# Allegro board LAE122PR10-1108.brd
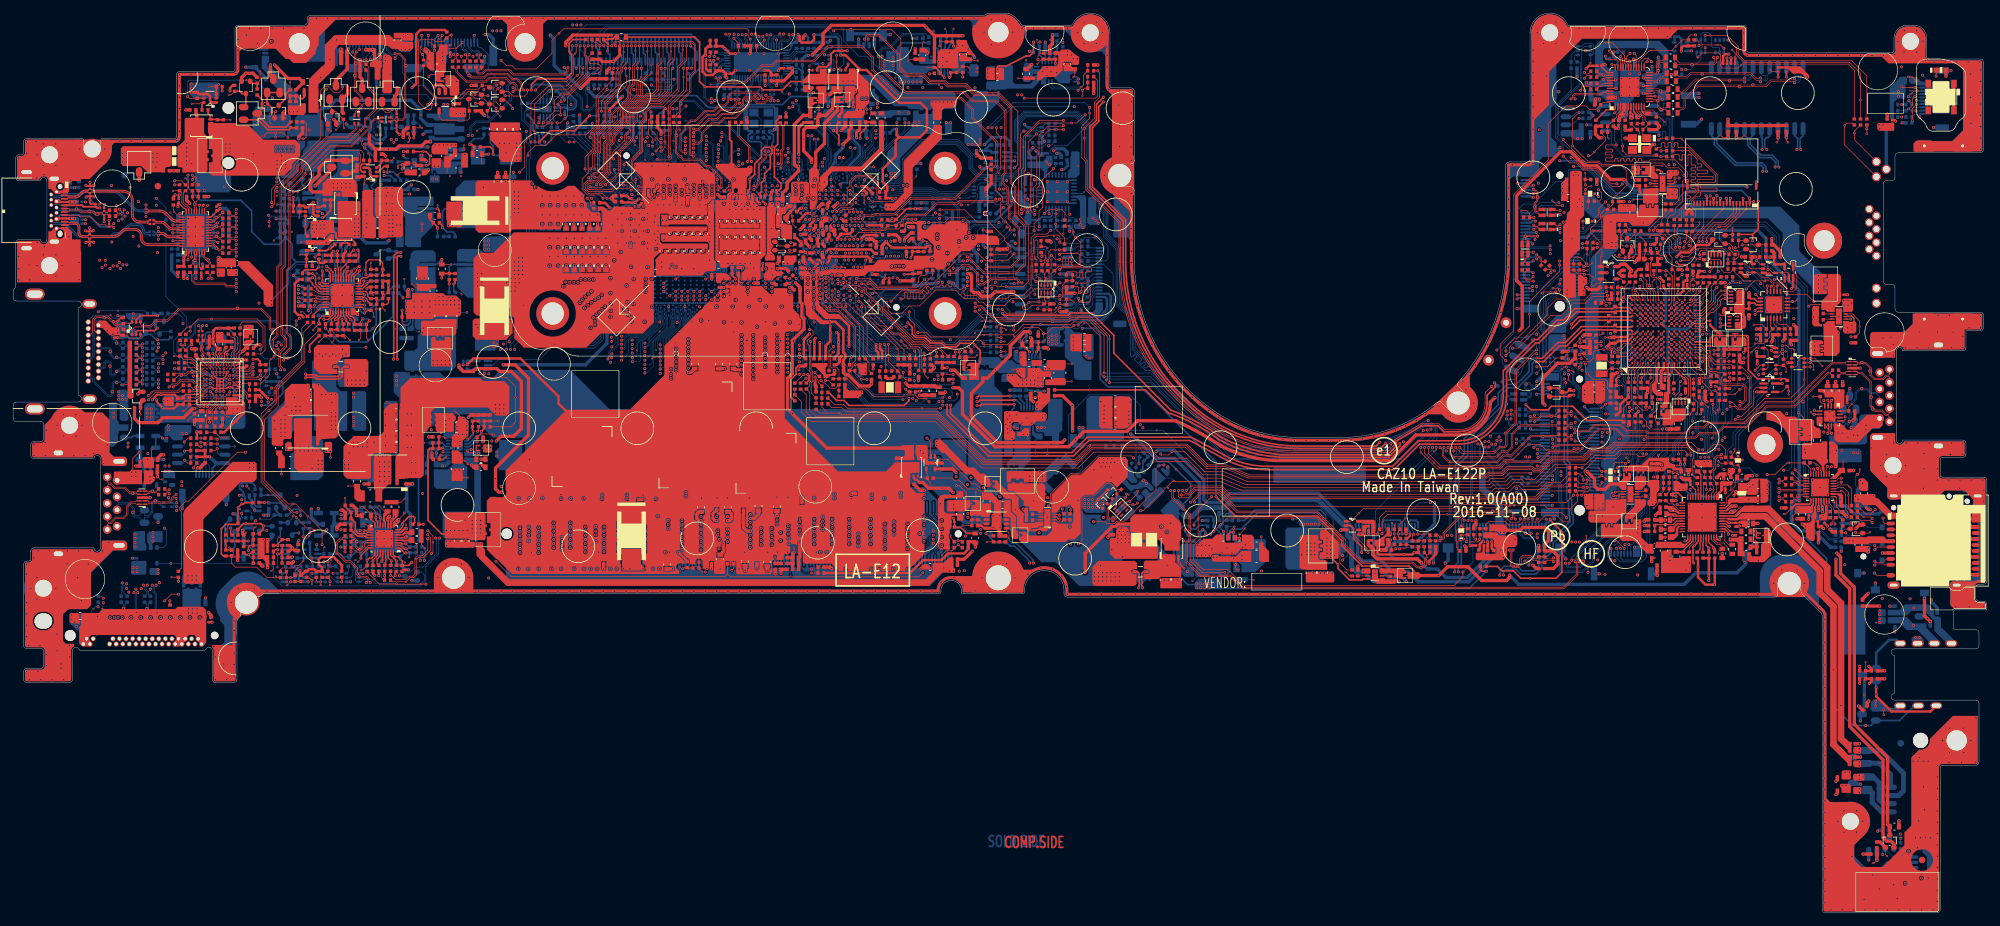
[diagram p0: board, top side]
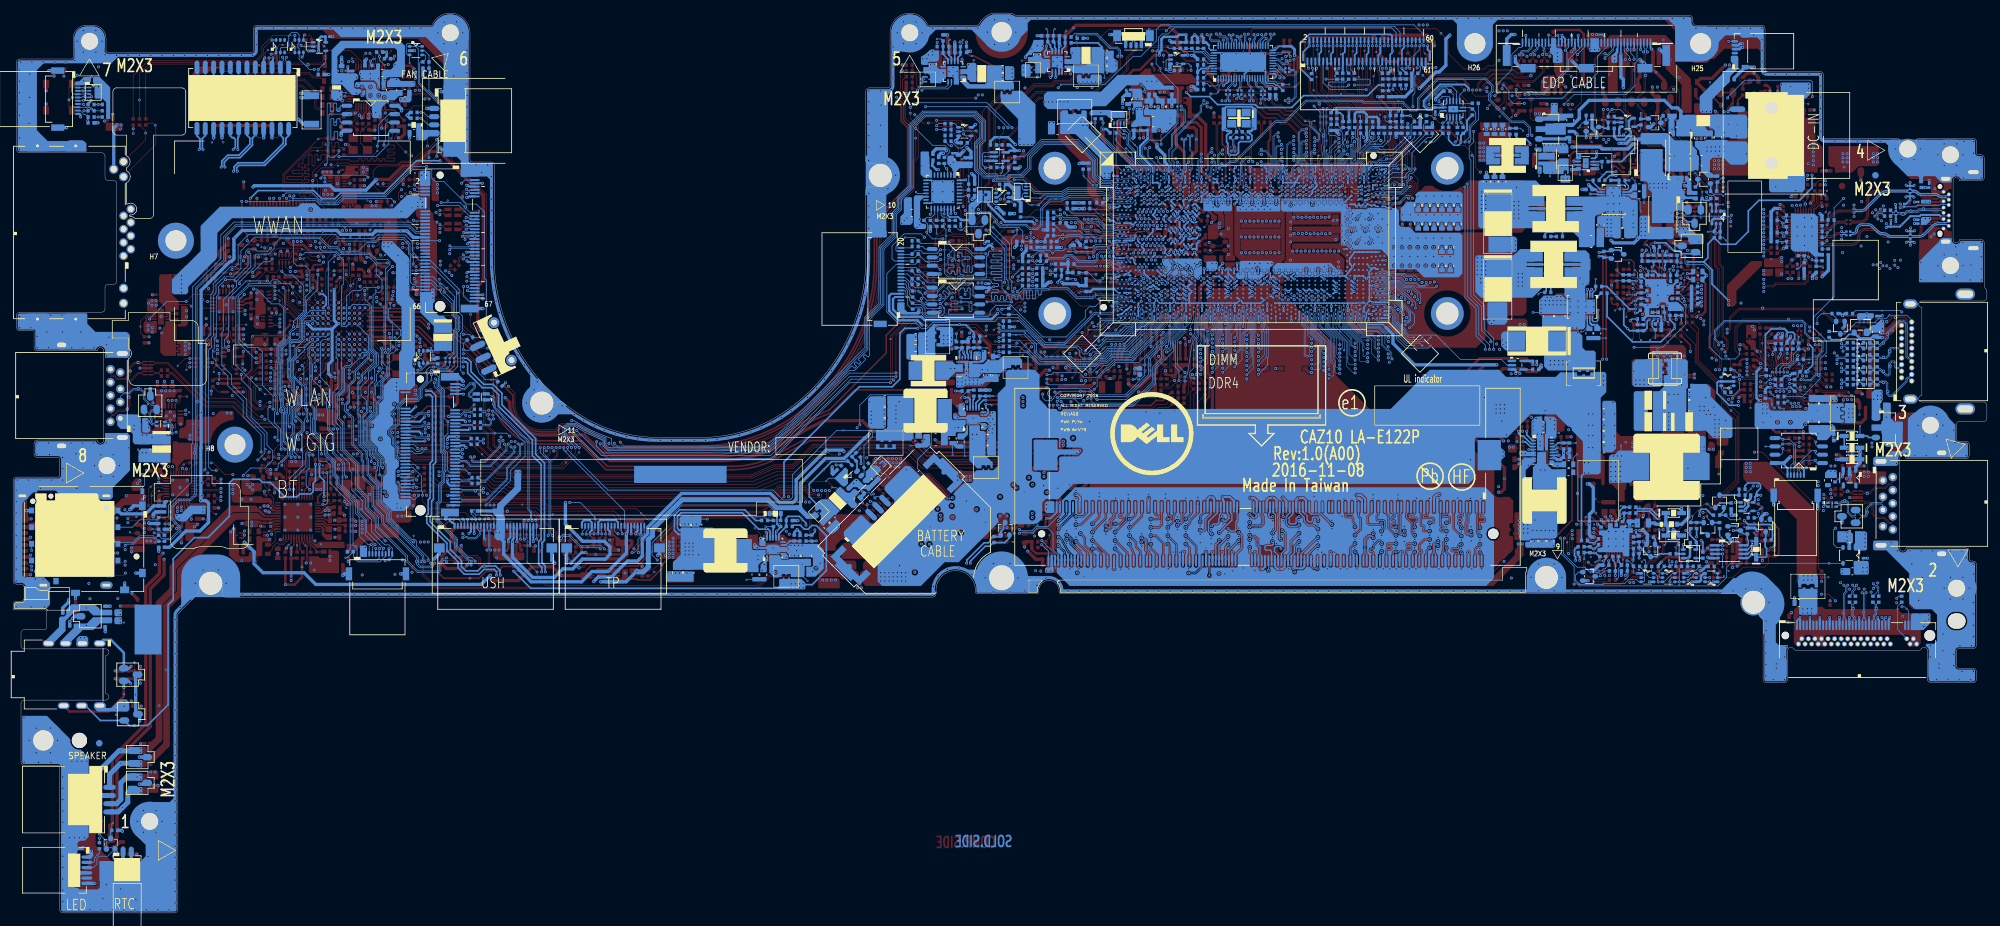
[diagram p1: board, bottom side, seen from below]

Outline 300.7 x 137.2 mm; copper layers: TOP, GND1, IN1, VCC, IN2, IN3, GND2, BOTTOM. Coordinates in mm from the lower left corner of the outline.

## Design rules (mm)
net group 20: nets DDR_DRAMRST#_R EMMC_RCOMP
net group DIFFPAIR0: nets PCIE_PTX_C_DRX_N1 PCIE_PTX_C_DRX_P1
net group DIFFPAIR1: nets PCIE_PTX_DRX_N1 PCIE_PTX_DRX_P1
net group DIFFPAIR2: nets PCIE_PRX_DTX_N1 PCIE_PRX_DTX_P1
net group DIFFPAIR3: nets PCIE_PRX_C_DTX_N1 PCIE_PRX_C_DTX_P1
net group DIFFPAIR4: nets SATA_PRX_DTX_N1 SATA_PRX_DTX_P1
net group EXPANDER_GPU_SMCLK: nets EXPANDER_GPU_SMCLK EXPANDER_GPU_SMDAT
net group HDMI_CTRL_CLK: nets HDMI_CTRL_CLK HDMI_CTRL_DATA
net group HDMI_L_CLK: nets HDMI_L_CLKN HDMI_L_CLKP
net group HDMI_L_TX_0: nets HDMI_L_TX_N0 HDMI_L_TX_P0
net group HDMI_L_TX_1: nets HDMI_L_TX_N1 HDMI_L_TX_P1
net group HDMI_L_TX_2: nets HDMI_L_TX_N2 HDMI_L_TX_P2
net group INT_SPK_L: nets INT_SPK_L+ INT_SPK_L-
net group INT_SPK_R: nets INT_SPK_R+ INT_SPK_R-
net group INT_SPKR_L: nets INT_SPKR_L+ INT_SPKR_L-
net group INT_SPKR_R: nets INT_SPKR_R+ INT_SPKR_R-
net group ISH_I2C2_SCL: nets ISH_I2C2_SCL ISH_I2C2_SDA
net group LAN_MDI0: nets LAN_MDIN0 LAN_MDIP0
net group LAN_MDI0_L: nets LAN_MDIN0_L LAN_MDIP0_L
net group LAN_MDI1: nets LAN_MDIN1 LAN_MDIP1
net group LAN_MDI1_L: nets LAN_MDIN1_L LAN_MDIP1_L
net group LAN_MDI2: nets LAN_MDIN2 LAN_MDIP2
net group LAN_MDI2_L: nets LAN_MDIN2_L LAN_MDIP2_L
net group LAN_MDI3: nets LAN_MDIN3 LAN_MDIP3
net group LAN_MDI3_L: nets LAN_MDIN3_L LAN_MDIP3_L
net group LPSS_UART2_XD: nets LPSS_UART2_RXD LPSS_UART2_TXD
net group MEM_SMB: nets MEM_SMBCLK MEM_SMBDATA
net group MSCLK: nets MSCLK MSDATA
net group PACIE: nets CLK_PCIE_N0 CLK_PCIE_P0
net group PBAT_CHARGER_SMB: nets PBAT_CHARGER_SMBCLK PBAT_CHARGER_SMBDAT
net group PCIE_PRX_C_DTX_9: nets PCIE_PRX_C_DTX_N9 PCIE_PRX_C_DTX_P9
net group PCIE_PRX_DTX_3: nets PCIE_PRX_DTX_N3 PCIE_PRX_DTX_P3
net group PCIE_PRX_DTX_9: nets PCIE_PRX_DTX_N9 PCIE_PRX_DTX_P9
net group PCIE_PTX_C_DRX_3: nets PCIE_PTX_C_DRX_N3 PCIE_PTX_C_DRX_P3
net group PCIE_PTX_C_DRX_4: nets PCIE_PTX_C_DRX_N4 PCIE_PTX_C_DRX_P4
net group PCIE_PTX_C_DRX_9: nets PCIE_PTX_C_DRX_N9 PCIE_PTX_C_DRX_P9
net group PCIE_PTX_DRX_3: nets PCIE_PTX_DRX_N3 PCIE_PTX_DRX_P3
net group PCIE_PTX_DRX_9: nets PCIE_PTX_DRX_N9 PCIE_PTX_DRX_P9
net group REM_DIODE1: nets REM_DIODE1_N REM_DIODE1_P
net group REM_DIODE2: nets REM_DIODE2_N REM_DIODE2_P
net group REM_DIODE4: nets REM_DIODE4_N REM_DIODE4_P
net group RJ45_MDI0: nets RJ45_MDIN0 RJ45_MDIP0
net group RJ45_MDI1: nets RJ45_MDIN1 RJ45_MDIP1
net group RJ45_MDI2: nets RJ45_MDIN2 RJ45_MDIP2
net group RJ45_MDI3: nets RJ45_MDIN3 RJ45_MDIP3
net group SENSE: nets VCC_GT_SENSE VSS_GT_SENSE
net group SML0_SMB: nets SML0_SMBCLK SML0_SMBDATA
net group SML1_SMB: nets SML1_SMBCLK SML1_SMBDATA
net group SW_USB20_1: nets SW_USB20_N1 SW_USB20_P1
net group TBTA_AUX_C: nets TBTA_AUXN_C TBTA_AUXP_C
net group TBTA_LSX_R: nets TBTA_LSRX_R TBTA_LSTX_R
net group UPD1_SMBD: nets UPD1_SMBCLK_Q UPD1_SMBDAT_Q
net group USB3_PRX_C_DTX_P6: nets USB3_PRX_C_DTX_N6 USB3_PRX_C_DTX_P6
net group USB3_PRX_DTX_1: nets USB3_PRX_DTX_N1 USB3_PRX_DTX_P1
net group USB3_PRX_DTX_2: nets USB3_PRX_DTX_N2 USB3_PRX_DTX_P2
net group USB3_PRX_DTX_3: nets USB3_PRX_DTX_N3 USB3_PRX_DTX_P3
net group USB3_PRX_L_DTX_2: nets USB3_PRX_L_DTX_N2 USB3_PRX_L_DTX_P2
net group USB3_PTX_C_DRX_1: nets USB3_PTX_C_DRX_N1 USB3_PTX_C_DRX_P1
net group USB3_PTX_C_DRX_2: nets USB3_PTX_C_DRX_N2 USB3_PTX_C_DRX_P2
net group USB3_PTX_C_DRX_3: nets USB3_PTX_C_DRX_N3 USB3_PTX_C_DRX_P3
net group USB3_PTX_DRX_1: nets USB3_PTX_DRX_N1 USB3_PTX_DRX_P1
net group USB3_PTX_DRX_2: nets USB3_PTX_DRX_N2 USB3_PTX_DRX_P2
net group USB3_PTX_L_DRX_2: nets USB3_PTX_L_DRX_N2 USB3_PTX_L_DRX_P2
net group USB20_1: nets USB20_N1 USB20_P1
net group USB20_2: nets USB20_N2 USB20_P2
net group USB20_2_R: nets USB20_N2_R USB20_P2_R
net group USB20_4: nets USB20_N4 USB20_P4
net group USB20_4_L: nets USB20_N4_L USB20_P4_L
net group USB20_5: nets USB20_N5 USB20_P5
net group USB20_5_R: nets USB20_N5_R USB20_P5_R
net group USB20_7_L: nets USB20_N7_L USB20_P7_L
net group USB20_8: nets USB20_N8 USB20_P8
net group USB20_8_R: nets USB20_N8_R USB20_P8_R
net group USB20_10: nets USB20_N10 USB20_P10
net group VCCSENSE: nets VCCSENSE VSSSENSE
net group VSA_SEN: nets VSA_SEN+ VSA_SEN-
net group VSSIO_SENSE: nets VCCIO_SENSE VSSIO_SENSE
net group 10: nets AUD_HP_NB_SENSE AUD_HP_OUT_L AUD_HP_OUT_L1 AUD_HP_OUT_R AUD_HP_OUT_R1 AUD_SENSE_A
net group 15: nets BC_CLK_ECE1117 CLK_TP_SIO_R CPU_DP2_CTRL_CLK CPU_XDP_TCLK DAT_TP_SIO_I2C_CLK DDR_XDP_WAN_SMBCLK DMIC_CLK0 DMIC_CLK_CODEC ESPI_CLK_5105 HDA_BIT_CLK HDA_BIT_CLK_R I2C1_SCK_TP_R JTAG_CLK PCH_JTAG_TCK PCI_CLK_LPC1 SUSCLK SUSCLK_R USH_SMBCLK WIGIG_32KHZ XCLK_BIASREF XDP_JTAGX
net group AR-90H: nets TBTA_RX1N TBTA_RX1P TBTA_RX2N TBTA_RX2P TBTA_TX1N TBTA_TX1N_C TBTA_TX1P TBTA_TX1P_C TBTA_TX2N TBTA_TX2N_C TBTA_TX2P TBTA_TX2P_C
net group AR-TBT: nets TBTA_BOT_N TBTA_BOT_N_R TBTA_BOT_P TBTA_BOT_P_R TBTA_TOP_N TBTA_TOP_N_R TBTA_TOP_P TBTA_TOP_P_R
net group ASYNC: nets H_CATERR# H_PROCHOT# H_PROCHOT#_R H_THERMTRIP# H_VCCST_PWRGD_XDP PCH_PLTRST# PCH_PLTRST#_5105 PCH_PLTRST#_AND PCH_PLTRST#_EC PLTRST_LAN# PLTRST_TPM# THERMATRIP1# THERMATRIP2# VCCST_PWRGD XDP_OBS0 XDP_OBS0_R XDP_OBS1 XDP_OBS1_R
net group DDR_XDP_WAN_SMB: nets DDR_XDP_WAN_SMBDAT
net group DDRA_CKE: nets DDR_A_CKE0 DDR_A_CKE1 DDR_A_CKE2 DDR_A_CKE3
net group DDRA_CLK: nets DDR_A_CLK0 DDR_A_CLK1 DDR_A_CLK#0 DDR_A_CLK#1
net group DDRA_CMD: nets DDR_A_ACT# DDR_A_ALERT# DDR_A_BA0 DDR_A_BA1 DDR_A_BG0 DDR_A_BG1 DDR_A_MA0 DDR_A_MA1 DDR_A_MA2 DDR_A_MA3 DDR_A_MA4 DDR_A_MA5 DDR_A_MA6 DDR_A_MA7 DDR_A_MA8 DDR_A_MA9 DDR_A_MA10 DDR_A_MA11 DDR_A_MA12 DDR_A_MA13 DDR_A_MA14 DDR_A_MA15 DDR_A_MA16 DDR_A_PARITY
net group DDRA_CTL: nets DDR_A_CS#0 DDR_A_CS#1 DDR_A_ODT0 DDR_A_ODT1
net group DDRA_D0: nets DDR_A_D0 DDR_A_D1 DDR_A_D2 DDR_A_D3 DDR_A_D4 DDR_A_D5 DDR_A_D6 DDR_A_D7
net group DDRA_D1: nets DDR_A_D8 DDR_A_D9 DDR_A_D10 DDR_A_D11 DDR_A_D12 DDR_A_D13 DDR_A_D14 DDR_A_D15
net group DDRA_D2: nets DDR_A_D16 DDR_A_D17 DDR_A_D18 DDR_A_D19 DDR_A_D20 DDR_A_D21 DDR_A_D22 DDR_A_D23
net group DDRA_D3: nets DDR_A_D24 DDR_A_D25 DDR_A_D26 DDR_A_D27 DDR_A_D28 DDR_A_D29 DDR_A_D30 DDR_A_D31
net group DDRA_D4: nets DDR_A_D32 DDR_A_D33 DDR_A_D34 DDR_A_D35 DDR_A_D36 DDR_A_D37 DDR_A_D38 DDR_A_D39
net group DDRA_D5: nets DDR_A_D40 DDR_A_D41 DDR_A_D42 DDR_A_D43 DDR_A_D44 DDR_A_D45 DDR_A_D46 DDR_A_D47
net group DDRA_D6: nets DDR_A_D48 DDR_A_D49 DDR_A_D50 DDR_A_D51 DDR_A_D52 DDR_A_D53 DDR_A_D54 DDR_A_D55
net group DDRA_D7: nets DDR_A_D56 DDR_A_D57 DDR_A_D58 DDR_A_D59 DDR_A_D60 DDR_A_D61 DDR_A_D62 DDR_A_D63
net group DDRA_DQS: nets DDR_A_DQS0 DDR_A_DQS1 DDR_A_DQS2 DDR_A_DQS3 DDR_A_DQS4 DDR_A_DQS5 DDR_A_DQS6 DDR_A_DQS7 DDR_A_DQS#0 DDR_A_DQS#1 DDR_A_DQS#2 DDR_A_DQS#3 DDR_A_DQS#4 DDR_A_DQS#5 DDR_A_DQS#6 DDR_A_DQS#7
net group DIFF_CLK: nets CLK_ITPXDP_N CLK_ITPXDP_N_R CLK_ITPXDP_P CLK_ITPXDP_P_R CLK_PCIE_N1 CLK_PCIE_N2 CLK_PCIE_N3 CLK_PCIE_N4 CLK_PCIE_P1 CLK_PCIE_P2 CLK_PCIE_P3 CLK_PCIE_P4 XTAL24_IN XTAL24_OUT
net group DMIC_CLK: nets DMIC0
net group DP: nets CPU_DP1_AUXN CPU_DP1_AUXP CPU_DP1_N0 CPU_DP1_N1 CPU_DP1_N2 CPU_DP1_N3 CPU_DP1_P0 CPU_DP1_P1 CPU_DP1_P2 CPU_DP1_P3 CPU_DP2_AUXN CPU_DP2_AUXN_C CPU_DP2_AUXP CPU_DP2_AUXP_C CPU_DP2_N0 CPU_DP2_N0_C CPU_DP2_N1 CPU_DP2_N1_C CPU_DP2_N2 CPU_DP2_N2_C CPU_DP2_N3 CPU_DP2_N3_C CPU_DP2_P0 CPU_DP2_P0_C CPU_DP2_P1 CPU_DP2_P1_C CPU_DP2_P2 CPU_DP2_P2_C CPU_DP2_P3 CPU_DP2_P3_C HDMI_CLKN HDMI_CLKP HDMI_TX_N0 HDMI_TX_N1 HDMI_TX_N2 HDMI_TX_P0 HDMI_TX_P1 HDMI_TX_P2 SW2_DP1_AUXN SW2_DP1_AUXN_C SW2_DP1_AUXP SW2_DP1_AUXP_C SW2_DP1_N0 SW2_DP1_N0_C SW2_DP1_N1 SW2_DP1_N1_C SW2_DP1_N2 SW2_DP1_N2_C SW2_DP1_N3 SW2_DP1_N3_C SW2_DP1_P0 SW2_DP1_P0_C SW2_DP1_P1 SW2_DP1_P1_C SW2_DP1_P2 SW2_DP1_P2_C SW2_DP1_P3 SW2_DP1_P3_C SW2_DP2_AUXN SW2_DP2_AUXN_C SW2_DP2_AUXP SW2_DP2_AUXP_C SW2_DP2_N0 SW2_DP2_N0_C SW2_DP2_N1 SW2_DP2_N1_C SW2_DP2_N2 SW2_DP2_N2_C SW2_DP2_N3 SW2_DP2_N3_C SW2_DP2_P0 SW2_DP2_P0_C SW2_DP2_P1 SW2_DP2_P1_C SW2_DP2_P2 SW2_DP2_P2_C SW2_DP2_P3 SW2_DP2_P3_C
net group EDP: nets EDP_AUXN EDP_AUXN_C EDP_AUXP EDP_AUXP_C EDP_TXN0 EDP_TXN0_C EDP_TXN1 EDP_TXN1_C EDP_TXP0 EDP_TXP0_C EDP_TXP1 EDP_TXP1_C
net group ESPI: nets ESPI_CS# ESPI_IO0 ESPI_IO1 ESPI_IO2 ESPI_IO3
net group HDA_5_15: nets HDA_RST# HDA_RST#_R HDA_SDIN0 HDA_SDIN0_R HDA_SDOUT HDA_SDOUT_R HDA_SYNC HDA_SYNC_R
net group I2C: nets CLK_TP_SIO_I2C_DAT I2C1_SCK_TP I2C1_SDA_TP
net group PCIE: nets PCIE_PRX_DTX_N4 PCIE_PRX_DTX_P4 PCIE_PTX_DRX_N4 PCIE_PTX_DRX_P4
net group SATA: nets PCIE_PRX_DTX_N11 PCIE_PRX_DTX_N12 PCIE_PRX_DTX_P11 PCIE_PRX_DTX_P12 PCIE_PTX_C_DRX_N11 PCIE_PTX_C_DRX_N12 PCIE_PTX_C_DRX_P11 PCIE_PTX_C_DRX_P12 PCIE_PTX_DRX_N11 PCIE_PTX_DRX_N12 PCIE_PTX_DRX_P11 PCIE_PTX_DRX_P12 SATA_PTX_C_DRX_N1 SATA_PTX_C_DRX_P1 SATA_PTX_DRX_N1 SATA_PTX_DRX_P1
net group SD: nets SD/MMCCD# SD/MMCCLK SD/MMCCLK_R SD/MMCCMD SD/MMCDAT2 SD/MMCDAT2_R SD/MMCDAT3 SD/MMCDAT3_R SDWP
net group SD-DIFF: nets SD/MMCDAT0/RCLK+ SD/MMCDAT0/RCLK+_R SD/MMCDAT1/RCLK- SD/MMCDAT1/RCLK-_R SD_UHS2_D0N SD_UHS2_D0P SD_UHS2_D1N SD_UHS2_D1P
net group SMB: nets CPU_DP1_CTRL_CLK CPU_DP1_CTRL_DATA CPU_DP2_CTRL_DATA PBAT_SMBCLK_C PBAT_SMBDAT_C PCH_SMB_ALERT# UPD1_SMBCLK UPD1_SMBDAT UPD1_SMBUS_ALERT# UPD2_SMBCLK UPD2_SMBDAT
net group SPI: nets PCH_SPI_CLK PCH_SPI_CLK_0_R PCH_SPI_CLK_1_R PCH_SPI_CLK_2_R PCH_SPI_CLK_R1 PCH_SPI_CS#0 PCH_SPI_CS#0_R1 PCH_SPI_CS#0_R2 PCH_SPI_CS#1 PCH_SPI_CS#1_R1 PCH_SPI_CS#1_R2 PCH_SPI_CS#2 PCH_SPI_CS#2_R PCH_SPI_D0 PCH_SPI_D0_0_R PCH_SPI_D0_1_R PCH_SPI_D0_2_R PCH_SPI_D0_R1 PCH_SPI_D1 PCH_SPI_D1_0_R PCH_SPI_D1_1_R PCH_SPI_D1_2_R PCH_SPI_D1_R1 PCH_SPI_D2 PCH_SPI_D2_0_R PCH_SPI_D2_1_R PCH_SPI_D2_R1 PCH_SPI_D3 PCH_SPI_D3_0_R PCH_SPI_D3_1_R PCH_SPI_D3_R1 PCH_SPI_DO2_XDP PCH_SPI_DO_XDP RESET_OUT#_R
net group SVID: nets H_CPU_SVIDALRT# VIDALERT_N VIDSCLK VIDSOUT
net group UART: nets ISH_UART0_CTS# ISH_UART0_CTS#_R ISH_UART0_RTS# ISH_UART0_RTS#_R ISH_UART0_RXD ISH_UART0_RXD_R ISH_UART0_TXD ISH_UART0_TXD_R
net group UIM: nets UIM_CLK UIM_DATA UIM_RESET
net group USB2.0: nets USB20_N1_R USB20_N7 USB20_N9 USB20_P1_R USB20_P7 USB20_P9
net group USB3.0: nets USB3_PRX_DTX_N6 USB3_PRX_DTX_P6 USB3_PTX_C_DRX_N6 USB3_PTX_C_DRX_P6 USB3_PTX_DRX_N3 USB3_PTX_DRX_N6 USB3_PTX_DRX_P3 USB3_PTX_DRX_P6
net group USH_SMB: nets USH_SMBDAT
nets with their own width: min track width 0.203; nets TBTA_CC1 TBTA_CC2
nets with their own width: min track width 0.254; nets +1.0V_APLLEBB +1.0V_PRIM_XDP +1.0V_VCCSTG +1.0V_VCCSTG_R +1.8V_3.3V_ALW_VTR3 +3.3V_1.8V_PGPPA +3.3V_1.8V_PGPPG +3.3V_ALW2 +3.3V_RUN_DIMM1 +3.3V_VCCHDA +3.3V_VDD_PIC +5V_ALW2 +5V_TBT_VBUS +5V_TBTA_VBUS_D +AC_IN ACIN_ISL88738 CSI2_COMP OTGEN/CMIN
nets with their own width: min track width 0.305; nets +RREF
nets with their own width: min track width 0.381; nets CFG_RCOMP CPU_POPIRCOMP EDP_COMP EDRAM_OPIO_RCOMP EOPIO_RCOMP HP_OUT_L HP_OUT_R PCH_POPIRCOMP PCIE_RCOMPN PCIE_RCOMPP SD_RCOMP SM_RCOMP0 SM_RCOMP1 SM_RCOMP2
nets with their own width: min track width 0.508; nets +0.6VSP +0.9V_LAN +1.0V_AMPHYPLL +1.0V_APLL +1.0V_CLK1 +1.0V_CLK2 +1.0V_CLK3 +1.0V_CLK4 +1.0V_CLK5 +1.0V_CLK6 +1.0V_DTS +1.0V_MPHYAON +1.0V_PRIM_CORE +1.0V_PRIM_COREP +1.0V_VCCST +1.0V_VCCST_C +1.0V_VCCSTG_C +1.0VO_DSW +1.2V_DDRP +1.2V_LDO +1.2V_MEM +1.2V_MEM_CPUCLK +1.8V_PGPPF +1.8V_PRIM +1.8V_RUN +1.8V_RUN_AUDIO +1.8V_RUN_UZ8 +1.8VALWP +1VALWP +1VALWP_B+ +1VS_VCCIOP +2.5V_MEM +2.5V_VIN +3.3V_1.8V_ESPI +3.3V_ALW +3.3V_ALW_DSW +3.3V_ALW_PCH +3.3V_ALW_PCH_UZ3 +3.3V_ALW_UE1 +3.3V_ALWP +3.3V_EC_PLL +3.3V_LAN_OUT +3.3V_LAN_UZ2 +3.3V_PDA_VOUT +3.3V_PGPPB +3.3V_PGPPC +3.3V_PGPPD +3.3V_PGPPE +3.3V_RTC_LDO +3.3V_RUN +3.3V_RUN_AUDIO +3.3V_RUN_AUDIO_DVDD +3.3V_RUN_AUDIO_IO +3.3V_RUN_AUDIO_UZ5 +3.3V_RUN_UZ3 +3.3V_SPI +3.3V_TBTA_FLASH +3.3V_TP +3.3V_TSP +3.3V_VDD_DCIN +5V_ALW +5V_ALW_PDA +5V_ALWP +5V_PD_VDD +5V_RUN +5V_RUN_AUDIO_UZ5 +BL_PWR_SRC +CHARGER_SRC +COINCELL +DC_IN +DC_IN_SS +DCIN_JACK +DCPRTC +DDR_VREF_A_CA +DDR_VREF_A_DQ +DDR_VREF_CA +EC_DEBUG_VCC +EDP_VDD +GND_CHASSIS +LCDVDD +MIC2-VREFO +PBATT +PECI_VREF +PWR_SRC +PWR_SRC_AC +PWR_SRC_R +REGCTL_PNP10 +RSVD_VCC3P3_1 +RTC_CELL +RTC_CELL_VBAT +SDC_IN +SDREG2 +SIM_PWR +TBTA_LDO_BMC +TBTA_VBUS_1 +VBUS_DC_SS +VCC1V8A_TBTA_LDO +VCC1V8D_TBTA_LDO +VCC_1P8 +VCC_CORE +VCC_CORE_G0 +VCC_CORE_G1 +VCC_GT +VCC_SA +VCC_SFR_OC +VCHGR +VDDA_AVDD1 +VR_CAP +VSS_PLL +Z4012 CPU_B+ GND GNDA Z2805 Z2806 Z2807 Z2808
nets with their own width: min track width 0.762; nets +1.0V_SRAM
nets with their own width: min track width 1.016; nets +0.6V_DDR_VTT +1.8V_RUN_CARD +3.3V_CAM +3.3V_MMI_IN +3.3V_RUN_CARD +VHDMI_VCC RING2 RING2_R SLEEVE SLEEVE_R
nets with their own width: min track width 1.524; nets +3.3V_LAN +5V_RUN_PVDD_L
nets with their own width: min track width 2.032; nets +1.0V_MPHYGT +3.3V_WLAN +3.3V_WLAN_UZ2 +3.3V_WWAN +5V_RUN_AUDIO +5V_RUN_UZ4 +5V_USB_CHG_PWR +USB_EX2_PWR
nets with their own width: min track width 2.54; nets +3.3V_WWAN_UZ4
nets with their own width: min track width 3.048; nets +1.0VS_VCCIO +3.3V_HDD_M2
nets with their own width: min track width 4.064; nets +1.0V_PRIM
nets with their own width: min track width 5.08; nets +TBTA_VBUS

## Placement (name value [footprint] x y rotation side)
CA1  -  [C_0402]  286.7 43.62 90 bottom
CA2  -  [C_0402]  283.09 35.7 0 top
CA3  -  [C_0402]  283.09 36.9 0 top
CA4  -  [C_0402]  286.7 45.85 90 bottom
CA5  -  [C_0402]  53.76 129.41 0 top
CA6  -  [C_0402]  53.76 128.53 180 top
CA7  -  [C_0201]  55.97 130.31 270 top
CA8  -  [C_0201]  252.44 55.8 270 top
CA9  -  [C_0603]  251.48 55.95 270 top
CA10  -  [C_0201]  260.27 64.72 0 top
CA12  -  [C_0402]  291.16 43.76 0 bottom
CA13  -  [C_0402]  293.14 45.71 270 bottom
CA19  -  [C_0402]  278.84 20.71 180 top
CA22  -  [C_0402]  279.65 23.76 0 top
CA23  -  [C_0402]  279.73 25.79 0 top
CA24  -  [C_0402]  278.84 18.68 180 top
CA25  -  [C_0603]  252.44 59.89 180 top
CA27  -  [C_0402]  251.8 63.78 270 top
CA28  -  [C_0402]  250.91 63.78 270 top
CA29  -  [C_0603]  261.9 54.75 90 top
CA31  -  [C_0603]  262.66 66.37 0 top
CA33  -  [C_0402]  257.71 67.31 90 top
CA35  -  [C_0402]  255.36 55.01 270 top
CA41  -  [C_0402]  252.69 63.78 270 top
CA43  -  [C_0603]  252.41 57.29 180 top
CA44  -  [C_0603]  252.41 58.49 180 top
CA45  -  [C_0201]  262.41 59.49 270 top
CA46  -  [C_0603]  263.68 59.38 0 top
CA47  -  [C_0201]  262.15 63.09 90 top
CA48  -  [C_0603]  265.14 63 0 top
CA49  -  [C_0603]  260.39 55.51 270 top
CA51  -  [C_0603]  253.39 55.07 270 top
CA52  -  [C_0603]  263.29 58.18 0 top
CA53  -  [C_0603]  256.63 67.32 90 top
CA54  -  [C_0402]  258.6 67.31 90 top
CA55  -  [C_0201]  255.52 65.29 180 top
CA56  -  [C_0603]  255.23 66.11 90 top
CA57  -  [C_0201]  262.47 57 90 top
CA58  -  [C_0603]  263.29 56.97 0 top
CA59  -  [C_0603]  265.14 64.21 0 top
CA60  -  [C_0201]  265.73 66.05 0 top
CA61  -  [C_0603]  260.63 65.48 90 top
CA62  -  [C_0402]  251.43 64.68 180 top
CA63  -  [C_0402]  265.63 65.29 0 top
CA64  -  [C_0402]  249.64 55.08 270 top
CA65  -  [C_0402]  265.63 55.83 0 top
CA66  -  [C_0402]  265.63 54.94 0 top
CA67  -  [C_0402]  249.58 67.56 90 top
CA68  -  [C_0402]  250.47 67.56 90 top
CA69  -  [C_0402]  263.54 54.68 0 top
CA72  -  [C_0402]  252.3 64.68 0 top
CC7  -  [C_0402]  156.6 102.5 0 top
CC8  -  [C_0402]  157.95 91.95 90 top
CC9  -  [C_0201]  152.04 101.83 90 bottom
CC10  -  [C_0201]  151.98 95.35 90 bottom
CC21  -  [C_0402]  114.31 119.1 0 bottom
CC22  -  [C_0402]  113.45 119.1 180 bottom
CC23  -  [C_0402]  135.1 81.74 180 top
CC24  -  [C_0402]  129.82 84.48 270 top
CC25  -  [C_0402]  128.24 82.69 0 top
CC26  -  [C_0402]  132.03 81.74 0 top
CC27  -  [C_0402]  119.09 78.99 270 top
CC28  -  [C_0201]  90.64 133.26 90 top
CC29  -  [C_0201]  91.21 133.26 90 top
CC30  -  [C_0201]  84.03 122.79 270 bottom
CC32  -  [C_0402]  89.37 131.09 270 top
CC33  -  [C_0402]  89.38 128.03 180 bottom
CC176  -  [C_0402]  117.63 94.87 90 top
CC177  -  [C_0402]  116.23 94.87 90 top
CC178  -  [C_0402]  109.79 94.88 180 top
CC179  -  [C_0402]  113.5 95.12 90 top
CC195  -  [C_0402]  122.59 120.53 180 top
CC199  -  [C_0402]  116.35 108.86 180 top
CC202  -  [C_0402]  119.37 106.93 180 top
CC203  -  [C_0402]  123.34 108.1 270 top
CC204  -  [C_0402]  132.54 96.09 0 top
CC205  -  [C_0402]  121.36 100.62 270 top
CC206  -  [C_0402]  120.74 102.56 90 top
CC207  -  [C_0402]  123.59 101.68 180 top
CC208  -  [C_0402]  123.39 103.4 0 top
CC209  -  [C_0402]  121.61 102.57 0 top
CC210  -  [C_0805]  140.71 119.45 0 bottom
CC211  -  [C_0402]  123.18 104.77 180 top
CC212  -  [C_0402]  132.4 101.47 180 top
CC213  -  [C_0402]  120.04 97.43 90 top
CC214  -  [C_0201]  131.81 84.59 0 top
CC215  -  [C_0402]  148.99 103 90 top
CC216  -  [C_0402]  127.86 119.33 180 bottom
CC217  -  [C_0402]  119.96 100.83 90 top
CC218  -  [C_0402]  121.43 104.79 180 top
CC219  -  [C_0805]  129.37 123.3 90 bottom
CC220  -  [C_0805]  125.94 123.8 270 bottom
CC221  -  [C_0805]  127.66 123.8 270 bottom
CC222  -  [C_0402]  126.95 104.15 0 top
CC223  -  [C_0201]  126.76 97.22 180 top
CC224  -  [C_0402]  131.6 98.26 270 top
CC225  -  [C_0805]  127.87 120.66 180 bottom
CC226  -  [C_0805]  124.17 123.8 270 bottom
CC250  -  [C_0402]  107.35 97.29 180 top
CC251  -  [C_0402]  107.59 96.29 270 top
CC252  -  [C_0402]  115.72 98.88 90 top
CC253  -  [C_0402]  114.83 98.88 90 top
CC264  -  [C_0402]  124.36 108.36 315 top
CC265  -  [C_0402]  124.32 99.95 180 top
CC266  -  [C_0402]  125.8 79.64 0 top
CC269  -  [C_0402]  91.35 128.09 180 top
CC270  -  [C_0201]  126.49 84.34 180 top
CC279  -  [C_0603]  138.96 80.34 270 top
CC280  -  [C_0603]  140.17 80.34 270 top
CC281  -  [C_0201]  131.13 125.49 180 bottom
CC288  -  [C_0402]  119.89 95.01 180 top
CC294  -  [C_0603]  103.85 84.4 270 top
CC295  -  [C_0603]  107.53 84.4 270 top
CC296  -  [C_0603]  109.73 84.4 270 top
CC297  -  [C_0402]  109.55 98.41 0 top
CC300  -  [C_0402]  85.37 118.87 90 bottom
CC301  -  [C_0402]  90 119.78 270 bottom
CC302  -  [C_0402]  148.11 114.45 270 bottom
CC303  -  [C_0402]  99.91 120.23 270 bottom
CC304  -  [C_0402]  99.02 120.23 270 bottom
CC305  -  [C_0402]  97.18 119.76 90 bottom
CC306  -  [C_0402]  88.23 131.09 270 top
CC307  -  [C_0402]  92.11 128.03 180 bottom
CC308  -  [C_0402]  97.29 121.42 0 top
CC310  -  [C_0402]  89.11 119.78 270 bottom
CC312  -  [C_0402]  95.41 119.77 180 bottom
CC313  -  [C_0201]  122.55 98.98 90 top
CC314  -  [C_0201]  124.52 104.72 180 top
CC316  -  [C_0402]  149.83 89.36 180 bottom
CC318  -  [C_0402]  141.69 102.39 270 bottom
CC319  -  [C_0402]  141.2 105.23 180 bottom
CC320  -  [C_0402]  133.26 104.79 180 top
CC321  -  [C_0402]  95.41 118.88 180 bottom
CC322  -  [C_0402]  136.92 71.07 0 top
CC323  -  [C_0402]  125.17 103.45 0 top
CC324  -  [C_0402]  137.06 97.43 270 top
CC325  -  [C_0402]  129.89 120.6 180 top
CC326  -  [C_0402]  137.01 100.85 180 top
CC331  -  [C_0402]  122.32 78.54 90 top
CC332  -  [C_0402]  120.85 79.88 90 top
CC333  -  [C_0402]  123.23 80.31 180 top
CD1  -  [C_0603]  108.86 62.56 270 top
CD2  -  [C_0603]  104.8 62.56 270 top
CD3  -  [C_0603]  111.53 54.3 270 top
CD4  -  [C_0603]  114.9 54.24 270 top
CD5  -  [C_0603]  116.36 62.69 270 top
CD6  -  [C_0603]  107.72 53.22 90 top
CD7  -  [C_0603]  99.66 53.86 270 top
CD8  -  [C_0603]  113.56 62.75 270 top
CD9  -  [C_0402]  89.98 54.13 270 top
CD10  -  [C_0402]  113.31 54.13 270 top
CD11  -  [C_0402]  111.28 62.32 270 top
CD12  -  [C_0402]  105.48 53.25 0 top
CD13  -  [C_0402]  95.34 63.9 270 top
CD14  -  [C_0402]  107.21 62.38 270 top
CD15  -  [C_0402]  128.29 63.05 90 top
CD16  -  [C_0402]  119.26 62.62 0 top
CD17  -  [C_D3]  94.19 60.68 270 top
CD18  -  [C_0402]  142.64 61.49 270 top
CD19  -  [C_0402]  142.64 62.61 90 top
CD20  -  [C_0603]  144.3 62.56 90 top
CD21  -  [C_0603]  144.3 61.54 270 top
CD22  -  [C_0603]  140.42 52.78 180 top
CD23  -  [C_0402]  142.95 53.92 0 top
CD24  -  [C_0402]  142.95 53.03 0 top
CD25  -  [C_0402]  118.76 53.29 0 top
CD26  -  [C_0402]  118.76 54.18 0 top
CD27  -  [C_0402]  143.42 58.88 180 top
CD28  -  [C_0201]  143.38 59.64 180 top
CD29  -  [C_0402]  102.7 52.63 90 top
CD31  -  [C_0402]  116.99 52.39 90 top
CD32  -  [C_0201]  69.15 84.15 180 bottom
CE1  -  [C_0402]  264.45 92.99 90 top
CE2  -  [C_0402]  264.45 92.12 270 top
CE3  -  [C_0402]  255.98 80.78 0 top
CE4  -  [C_0402]  256.87 79.51 0 top
CE5  -  [C_0402]  245.39 96.2 90 top
CE6  -  [C_0402]  245.39 98.89 270 top
CE8  -  [C_0402]  259.28 96.09 0 top
CE10  -  [C_0402]  243.36 79.5 90 top
CE11  -  [C_0201]  244.22 81.16 180 top
CE12  -  [C_0402]  244.24 76.86 270 top
CE13  -  [C_0201]  258.53 90.3 270 top
CE14  -  [C_0402]  243.86 87.78 270 top
CE15  -  [C_0201]  252.22 81.16 180 top
CE16  -  [C_0603]  253.58 75.26 270 top
CE17  -  [C_0603]  250.02 80.21 0 top
CE18  -  [C_0201]  250.43 81.16 0 top
CE19  -  [C_0201]  251.46 95.65 90 top
CE20  -  [C_0201]  251.65 78.24 180 top
CE21  -  [C_0201]  258.53 87.04 270 top
CE22  -  [C_0201]  263.9 86.62 270 top
CE23  -  [C_0201]  244.6 87.81 270 top
CE24  -  [C_0402]  244.05 89.62 270 top
CE25  -  [C_0201]  255.04 96.44 270 top
CE26  -  [C_0402]  243.1 91.08 270 top
CE27  -  [C_0402]  244.05 92.48 270 top
CE28  -  [C_0402]  243.61 83.02 270 top
CE29  -  [C_0402]  243.61 83.95 90 top
CE30  -  [C_0402]  248.69 101.04 180 top
CE31  -  [C_0402]  254.79 80.8 270 top
CE32  -  [C_0603]  238.91 118.95 0 bottom
CE35  -  [C_0402]  119.08 101.05 90 top
CE36  -  [C_0402]  267.03 101.86 0 top
CE37  -  [C_0402]  237.13 79.78 270 top
CE38  -  [C_0402]  244.45 93.61 180 top
CE39  -  [C_0402]  58.35 99.96 90 bottom
CE40  -  [C_0402]  252.74 98.12 0 top
CE46  -  [C_0402]  151.28 56.45 90 bottom
CE47  -  [C_0402]  255.93 98.77 270 top
CE52  -  [C_0402]  264.83 100.02 180 top
CE53  -  [C_0402]  268.29 100.02 0 top
CE54  -  [C_0402]  249.01 80.92 270 top
CE57  -  [C_0402]  247.1 74.86 90 top
CE59  -  [C_0402]  252.5 74.7 270 top
CE60  -  [C_0402]  263.05 85.96 270 top
CE61  -  [C_0402]  271.69 87.3 90 top
CE62  -  [C_0402]  249.72 78.62 180 top
CE500  -  [C_0402]  270.79 89.08 0 top
CE503  -  [C_0402]  237.35 128.8 0 bottom
CI1  -  [C_1206]  19.58 57.35 0 bottom
CI3  -  [C_0201]  19.48 65.54 0 top
CI4  -  [C_0402]  22.19 64.65 0 top
CI5  -  [C_0402]  22.19 63.76 0 top
CI6  -  [C_0603]  19.77 52.08 0 bottom
CI7  -  [C_0201]  18.88 53.5 90 bottom
CI13  -  [C_0402]  278.1 82.75 180 top
CI14  -  [C_1206]  280.76 71.96 270 bottom
CI16  -  [C_0402]  278.1 81.86 180 top
CI17  -  [C_0201]  281.43 75.19 180 bottom
CI19  -  [C_0201]  278.81 78.75 0 top
CI29  -  [C_0402]  229.89 98.96 270 top
CI30  -  [C_0402]  230.78 98.96 270 top
CI31  -  [C_0402]  278.73 79.5 90 top
CI32  -  [C_B2]  278.09 72.1 90 bottom
CI33  -  [C_0603]  277.65 78.94 90 top
CI34  -  [C_0603]  276.44 78.94 90 top
CI43  -  [C_0402]  281.53 73.54 180 bottom
CI44  -  [C_0402]  281.53 74.43 180 bottom
CI45  -  [C_0402]  19.32 66.3 0 top
CI46  -  [C_0402]  19.32 67.19 0 top
CL1  -  [C_0402]  240.36 128.34 0 top
CL2  -  [C_0402]  240.36 127.46 0 top
CL3  -  [C_0201]  249.71 127.8 90 bottom
CL4  -  [C_0603]  250.66 127.71 90 bottom
CL5  -  [C_0402]  240.36 126.5 0 top
CL6  -  [C_0402]  240.36 125.61 0 top
CL7  -  [C_0201]  244.56 120.76 270 top
CL8  -  [C_0201]  248.88 127.8 90 bottom
CL9  -  [C_0201]  247.84 125.23 180 bottom
CL10  -  [C_0201]  242 129.17 180 top
CL11  -  [C_0201]  244.4 126.5 0 bottom
CL12  -  [C_0603]  243.74 128.09 0 bottom
CL13  -  [C_0402]  247.43 119.45 180 top
CL14  -  [C_0402]  248.3 119.45 0 top
CL15  -  [C_0201]  253.11 133.61 180 bottom
CL16  -  [C_0201]  261.11 129.47 180 top
CL17  -  [C_0201]  262.32 129.47 180 top
CL18  -  [C_0402]  285.52 120.14 90 top
CL19  -  [C_0201]  286.28 120.31 90 top
CL20  -  [C_0201]  268.88 128.31 90 top
CL21  -  [C_0201]  270.15 128.31 90 top
CL22  -  [C_1808]  255.23 124.61 270 bottom
CL28  -  [C_0805]  243.04 124.64 90 bottom
CL29  -  [C_0402]  247.1 129.18 270 bottom
CL30  -  [C_0402]  246.91 126.43 90 bottom
CMOS1  SHORT PADS~D  [SHORTPADS-NPM]  129.06 82.56 90 bottom
CN60  -  [C_0402]  29.22 45.1 0 top
CN61  -  [C_0201]  29.2 44.33 0 top
CN62  -  [C_0201]  10.54 44.33 180 top
CN63  -  [C_0603]  10.95 45.29 180 top
CN64  -  [C_0603]  27.9 47.25 0 bottom
CN69  -  [C_0402]  20.92 47.38 90 bottom
CN70  -  [C_0402]  20.03 47.38 90 bottom
CN71  -  [C_0402]  17.36 47.38 90 bottom
CN72  -  [C_0402]  16.47 47.38 90 bottom
CR1  -  [C_0402]  276.05 69.68 0 top
CR2  -  [C_0201]  276.31 68.97 0 top
CR3  -  [C_0201]  274.33 59.68 0 top
CR4  -  [C_0402]  274.14 57.08 0 top
CR5  -  [C_0603]  272.57 61.49 270 top
CR6  -  [C_0201]  273.56 61.16 270 top
CR7  -  [C_0201]  275.92 60.04 270 top
CR11  -  [C_0402]  270.05 66.25 0 top
CR12  -  [C_0402]  270.05 65.29 0 top
CR13  -  [C_0402]  270.03 63.64 0 top
CR14  -  [C_0402]  270.04 62.7 0 top
CR15  -  [C_0402]  278.79 67.45 0 top
CR17  -  [C_0201]  282.09 55.79 90 top
CR18  -  [C_0603]  281.14 55.38 90 top
CR19  -  [C_0201]  282.29 61.8 90 top
CR20  -  [C_0603]  282.01 64.69 270 top
CR21  -  [C_0402]  278.53 58.1 180 top
CR22  -  [C_0402]  278.66 62.06 270 top
CR25  -  [C_0402]  274.14 58 0 top
CR26  -  [C_0402]  274.14 58.91 0 top
CR27  -  [C_0402]  276.05 70.62 0 top
CR28  -  [C_0402]  276.05 71.54 0 top
CT70  -  [C_0402]  29.23 69.56 270 top
CT71  -  [C_0402]  33.3 86.23 90 top
CT72  -  [C_0402]  35.56 83.4 90 top
CT73  -  [C_0402]  27.85 85.08 90 top
CT74  -  [C_0402]  35.7 86.12 0 top
CT75  -  [C_0805]  24.73 76.82 90 bottom
CT76  -  [C_0805]  26.44 76.82 90 bottom
CT77  -  [C_0805]  24.73 75.66 270 bottom
CT78  -  [C_0805]  26.44 75.66 270 bottom
CT80  -  [C_0201]  28.85 88.7 270 top
CT81  -  [C_0201]  28.28 88.7 270 top
CT82  -  [C_0603]  28.73 76.53 270 top
CT83  -  [C_0402]  29.74 85.28 90 top
CT84  -  [C_0603]  31.33 85.99 90 top
CT85  -  [C_0402]  25.06 77.54 180 top
CT86  -  [C_0402]  25.06 78.43 180 top
CT87  -  [C_0402]  29.3 80.48 270 bottom
CT88  -  [C_0201]  19.94 68.91 180 top
CT89  -  [C_0402]  20.23 68.15 180 top
CT90  -  [C_0402]  22.01 67.19 180 top
CT91  -  [C_0603]  24.22 65.23 90 bottom
CT92  -  [C_0402]  23.14 65.72 90 bottom
CT93  -  [C_0402]  23.33 72.01 90 bottom
CT94  -  [C_0603]  16.91 77.35 180 bottom
CT95  -  [C_0201]  21.4 105.62 180 top
CT96  -  [C_0201]  21.4 105.05 180 top
CT97  -  [C_0201]  21.4 103.33 180 bottom
CT98  -  [C_0201]  21.4 103.9 180 bottom
CT99  -  [C_0201]  9.87 108.41 0 bottom
CT100  -  [C_0201]  8.79 110.59 90 bottom
CT101  -  [C_0201]  9.87 105.69 0 bottom
CT102  -  [C_0201]  9.87 105.1 0 bottom
CT103  -  [C_0402]  32.87 100.59 180 top
CT104  -  [C_0402]  32.87 101.48 180 top
CT105  -  [C_0402]  32.87 102.37 180 top
CT106  -  [C_0402]  32.87 103.26 180 top
CT107  -  [C_0402]  32.87 104.15 180 top
CT108  -  [C_0402]  32.87 105.04 180 top
CT109  -  [C_0402]  32.87 105.93 180 top
CT110  -  [C_0402]  32.87 106.82 180 top
CT111  -  [C_0402]  27.84 97.67 90 top
CT112  -  [C_0402]  26.95 97.67 90 top
CT113  -  [C_0402]  30.44 97.67 90 top
CT114  -  [C_0402]  29.55 97.67 90 top
CT115  -  [C_0402]  28.22 111.02 270 top
CT116  -  [C_0402]  27.33 111.02 270 top
CT117  -  [C_0402]  31.96 98.83 270 top
CT118  -  [C_0201]  28.66 98.21 270 top
CT119  -  [C_0201]  31.2 98.66 270 top
CT120  -  [C_0201]  30.96 107.11 90 top
CT121  -  [C_0201]  25.23 108.3 90 top
CT122  -  [C_0402]  26 98.59 270 top
CT189  -  [C_0402]  9.99 110.62 90 bottom
CV1  -  [C_0402]  66.95 128.97 90 top
CV2  -  [C_0402]  67.84 128.97 90 top
CV3  -  [C_0402]  68.73 128.97 90 top
CV4  -  [C_0402]  69.62 128.97 90 top
CV5  -  [C_0402]  70.51 128.97 90 top
CV6  -  [C_0402]  71.4 128.97 90 top
CV11  -  [C_0603]  58.57 132.34 90 top
CV12  -  [C_0201]  66 131.2 0 top
CV13  -  [C_0402]  42.19 123.72 270 top
CV14  -  [C_0402]  43.08 124.59 90 top
CV15  -  [C_0603]  45.55 126.69 180 top
CV16  -  [C_0603]  65.24 128.92 180 top
CV17  -  [C_0402]  67.97 122.49 90 top
CV18  -  [C_0402]  50.9 130.44 180 top
CV19  -  [C_0402]  50.9 129.55 180 top
CV20  -  [C_0402]  64.74 130.88 180 top
CV21  -  [C_0402]  64.74 130 180 top
CV22  -  [C_0402]  56.55 128.34 180 top
CV23  -  [C_0402]  56.55 127.46 180 top
CV24  -  [C_0402]  60.6 132.4 90 top
CV25  -  [C_0402]  59.71 132.4 90 top
CV31  -  [C_0402]  21.27 80.53 180 bottom
CV32  -  [C_0402]  21.27 81.42 180 bottom
CV33  -  [C_0402]  21.27 82.37 180 bottom
CV34  -  [C_0402]  21.27 83.26 180 bottom
CV35  -  [C_0402]  21.27 86.05 180 bottom
CV36  -  [C_0402]  21.27 86.94 180 bottom
CV37  -  [C_0402]  20.36 84.21 0 bottom
CV38  -  [C_0402]  20.36 85.1 0 bottom
CV39  -  [C_0201]  17.41 91.02 180 bottom
CV40  -  [C_0201]  15.39 88.25 270 top
CV41  -  [C_0603]  16.91 89.29 270 bottom
CV81  -  [C_0402]  106.18 133.04 0 top
CV82  -  [C_0402]  116.36 126.87 90 top
CV83  -  [C_0201]  118.04 128.79 180 top
CV84  -  [C_0201]  108.57 127.96 0 top
CV85  -  [C_0201]  119.81 133.3 0 top
CV86  -  [C_0201]  115.91 124.81 90 bottom
CV87  -  [C_0201]  115.34 124.81 90 bottom
CV88  -  [C_0201]  114.13 124.81 90 bottom
CV89  -  [C_0201]  113.56 124.81 90 bottom
CV90  -  [C_0201]  112.36 124.75 90 bottom
CV91  -  [C_0201]  111.78 124.75 90 bottom
CV92  -  [C_0201]  110.58 124.75 90 bottom
CV93  -  [C_0201]  110.01 124.75 90 bottom
CV94  -  [C_0201]  106.28 128.22 0 bottom
CV95  -  [C_0201]  106.28 128.79 0 bottom
CV96  -  [C_0402]  109.24 125.69 270 bottom
CV145  -  [C_0402]  229.5 76.78 0 bottom
CV146  -  [C_0402]  229.5 75.89 0 bottom
CV147  -  [C_0402]  229.5 73.92 0 bottom
CV148  -  [C_0402]  229.5 74.81 0 bottom
CV149  -  [C_0402]  235.51 75.7 0 top
CV150  -  [C_0402]  235.51 76.59 0 top
CV152  -  [C_0402]  235.51 74.75 0 top
CV153  -  [C_0402]  235.51 73.86 0 top
CV156  -  [C_0402]  235.51 72.97 0 top
CV157  -  [C_0402]  235.51 72.08 0 top
CZ1  -  [C_0201]  56.51 129.11 180 top
CZ2  -  [C_0201]  50.73 131.2 180 top
CZ3  -  [C_0402]  39.41 127.07 180 bottom
CZ10  -  [C_0402]  234.05 98.7 135 top
CZ11  -  [C_0402]  233.42 98.09 135 top
CZ12  -  [C_0402]  230.01 72.34 0 bottom
CZ13  -  [C_0402]  230.01 71.45 0 bottom
CZ14  -  [C_0402]  229.88 66.37 0 bottom
CZ15  -  [C_0402]  229.88 65.48 0 bottom
CZ17  -  [C_0402]  237.76 94.37 0 top
CZ18  -  [C_0402]  237.76 95.26 0 top
CZ19  -  [C_0402]  237.76 96.15 0 top
CZ20  -  [C_0603]  237.58 108.98 180 top
CZ21  -  [C_0402]  237.76 97.04 0 top
CZ23  -  [C_0402]  237.59 110.06 180 top
CZ24  -  [C_0402]  237.59 110.95 180 top
CZ25  -  [C_0402]  237.59 111.83 180 top
CZ26  -  [C_B2]  235.23 89.14 90 bottom
CZ27  -  [C_0603]  241.57 79.94 180 top
CZ28  -  [C_0402]  241.35 77.98 180 top
CZ29  -  [C_0402]  241.35 78.87 180 top
CZ30  -  [C_0201]  241.23 80.91 180 top
CZ31  -  [C_0201]  241.11 61.73 180 top
CZ32  -  [C_0603]  246.85 106.12 90 top
CZ33  -  [C_0402]  241.34 62.49 180 top
CZ34  -  [C_0402]  241.34 63.38 180 top
CZ35  -  [C_0402]  244.88 106.23 90 top
CZ36  -  [C_0402]  245.77 106.23 90 top
CZ37  -  [C_0402]  278.53 62.06 270 bottom
CZ38  -  [C_0402]  278.53 57.59 90 bottom
CZ39  -  [C_0402]  278.52 56.67 270 bottom
CZ40  -  [C_0402]  278.53 60.29 270 bottom
CZ41  -  [C_0402]  277.65 62.06 270 bottom
CZ50  -  [C_0201]  161.26 113.96 180 bottom
CZ51  -  [C_0201]  157.61 115.25 90 bottom
CZ52  -  [C_0603]  156.68 114.22 90 bottom
CZ53  -  [C_0201]  163.26 105.76 0 bottom
CZ54  -  [C_0201]  156.32 105.73 270 bottom
CZ55  -  [C_0603]  163.1 106.74 0 bottom
CZ56  -  [C_0402]  160.96 105.6 270 bottom
CZ57  -  [C_0402]  155.65 114.23 90 bottom
CZ58  -  [C_0402]  154.77 114.23 90 bottom
CZ59  -  [C_0402]  163.21 108.81 0 bottom
CZ60  -  [C_0402]  163.21 107.86 0 bottom
CZ61  -  [C_0402]  224.36 58.57 270 top
CZ62  -  [C_0402]  232.43 54.29 90 top
CZ63  -  [C_0402]  232.43 53.43 270 top
CZ64  -  [C_0201]  225.28 56.02 0 top
CZ66  -  [C_0201]  223.45 56.02 180 top
CZ67  -  [C_0201]  224.66 56.02 180 top
CZ68  -  [C_0201]  225.14 58.42 270 top
CZ69  -  [C_0402]  225.58 55.27 270 top
CZ71  -  [C_0402]  223.29 55.33 270 top
CZ72  -  [C_0402]  224.62 55.27 270 top
CZ73  -  [C_0402]  225.91 58.52 270 top
CZ75  -  [C_0402]  161.47 114.78 180 bottom
CZ80  -  [C_0402]  209.97 55.32 180 top
CZ81  -  [C_0402]  212.24 56.2 90 top
CZ82  -  [C_0201]  206.53 59.55 270 top
CZ83  -  [C_0402]  208.67 56.21 0 top
CZ90  -  [C_0201]  208.72 56.93 0 top
CZ91  -  [C_0201]  205.95 59.55 270 top
CZ92  -  [C_0201]  206.5 58.37 180 top
CZ93  -  [C_0201]  265.71 84.82 270 top
CZ100  -  [C_0402]  124.99 126.71 270 top
CZ101  -  [C_0201]  127.98 124.26 270 top
CZ102  -  [C_0402]  136.35 65.35 0 top
CZ103  -  [C_0201]  137.08 70.31 0 top
CZ104  -  [C_0402]  141.5 67.69 90 top
CZ105  -  [C_0402]  120.61 126.77 270 top
CZ106  -  [C_0201]  123.75 124.72 0 top
CZ109  -  [C_0402]  248.7 110.88 180 top
CZ110  -  [C_0402]  248.7 111.77 180 top
CZ111  -  [C_0201]  249.86 113.29 0 top
CZ112  -  [C_0201]  154.93 58.37 0 top
CZ113  -  [C_0402]  155.29 59.89 180 top
CZ114  -  [C_0402]  155.29 60.78 180 top
CZ115  -  [C_0201]  155 61.54 180 top
CZ116  -  [C_0201]  275.97 89.61 180 top
CZ117  -  [C_0402]  275.77 90.43 180 top
CZ118  -  [C_0402]  275.77 91.39 180 top
CZ119  -  [C_0201]  278.31 94.24 0 top
CZ120  -  [C_0201]  210.59 51.29 270 top
CZ121  -  [C_0402]  209.83 51.33 270 top
CZ122  -  [C_0201]  248.54 109.8 180 top
CZ124  -  [C_0402]  275.77 92.28 180 top
CZ125  -  [C_0201]  248.59 65.42 0 top
CZ126  -  [C_0402]  248.74 64.46 0 top
CZ127  -  [C_0402]  248.74 63.57 0 top
CZ128  -  [C_0201]  248.59 62.62 0 top
CZ197  -  [C_0402]  204.87 51.37 90 top
CZ198  -  [C_0402]  240.36 111.83 0 top
DA1  -  [L03ESDL5V0CC3-2_SOT23-3]  281.75 36.33 90 bottom
DA2  -  [L03ESDL5V0CC3-2_SOT23-3]  281.68 30.3 90 bottom
DA3  -  [L03ESDL5V0CC3-2_SOT23-3]  290.43 45.22 270 bottom
DA6  -  [L03ESDL5V0CC3-2_SOT23-3]  280.29 23.76 90 bottom
DA7  -  [L03ESDL5V0CC3-2_SOT23-3]  280.29 19.82 90 bottom
DA8  -  [RB751S40T1G_SOD523-2]  262.79 69.67 270 top
DE1  -  [RB751S40T1G_SOD523-2]  238.97 120.15 0 bottom
DI1  -  [L05ESDL5V0NA-4_SLP2510P8-10-9]  20.08 62.32 270 top
DI2  -  [AZC199-02SPR7G_SOT23-3]  22.08 60.46 270 bottom
DI4  -  [L05ESDL5V0NA-4_SLP2510P8-10-9]  279.75 84.07 90 top
DI5  -  [AZC199-02SPR7G_SOT23-3]  279.8 78.84 0 bottom
DT1  -  [1N4148WS-7-F_SOD323-2]  19.33 69.16 0 bottom
DT2  -  [1N4148WS-7-F_SOD323-2]  19.33 70.94 0 bottom
DT3  -  [1N4148WS-7-F_SOD323-2]  21.73 72.72 180 bottom
DT4  -  [L30ESD24VC3-2_SOT23-3]  19.2 112.95 0 top
DT5  -  [ESD8011MUT5G_X3DFN2-2-S]  11.71 110.41 90 top
DT6  -  [ESD8011MUT5G_X3DFN2-2-S]  11.71 109.7 270 top
DT7  -  [ESD8011MUT5G_X3DFN2-2-S]  12.57 107.68 90 top
DT8  -  [ESD8011MUT5G_X3DFN2-2-S]  14.63 104.63 90 top
DT9  -  [ESD8011MUT5G_X3DFN2-2-S]  11.64 103.49 90 top
DT10  -  [ESD8011MUT5G_X3DFN2-2-S]  11.64 102.78 270 top
DT11  -  [ESD8011MUT5G_X3DFN2-2-S]  13.87 107.05 90 top
DT12  -  [ESD8011MUT5G_X3DFN2-2-S]  13.87 106.33 270 top
DT13  -  [ESD8011MUT5G_X3DFN2-2-S]  11.71 110.41 90 bottom
DT14  -  [ESD8011MUT5G_X3DFN2-2-S]  11.71 109.7 270 bottom
DT15  -  [ESD8011MUT5G_X3DFN2-2-S]  12.6 107.68 90 bottom
DT16  -  [ESD8011MUT5G_X3DFN2-2-S]  14.63 104.63 90 bottom
DT17  -  [ESD8011MUT5G_X3DFN2-2-S]  11.64 102.78 270 bottom
DT18  -  [ESD8011MUT5G_X3DFN2-2-S]  11.64 103.49 90 bottom
DT19  -  [ESD8011MUT5G_X3DFN2-2-S]  13.87 106.33 270 bottom
DT20  -  [ESD8011MUT5G_X3DFN2-2-S]  13.87 107.05 90 bottom
DV1  -  [BAT54CW_SOT323-3]  72.61 125.87 90 top
DV2  -  [BAT54CW_SOT323-3]  72.61 123.33 90 top
DV3  -  [BAT54CW_SOT323-3]  69.43 124.09 90 top
DV4  -  [AZC199-02SPR7G_SOT23-3]  53.17 125.77 180 top
DV7  -  [ESD8011MUT5G_X3DFN2-2-S]  58.42 120.63 270 top
DV8  -  [ESD8011MUT5G_X3DFN2-2-S]  58.42 121.35 90 top
DZ1  -  [RB751S40T1G_SOD523-2]  244.06 66.18 180 top
DZ2  -  [RB751S40T1G_SOD523-2]  244.06 67.32 180 top
DZ5  -  [RB751S40T1G_SOD523-2]  240.94 109.68 180 top
DZ6  -  [RB751S40T1G_SOD523-2]  240.56 105.48 180 top
DZ7  -  [RB751S40T1G_SOD523-2]  220.62 57.6 90 top
FD1  -  [FIDUCIAL_C40M80]  22.06 110.82 0 top
FD2  -  [FIDUCIAL_C40M80]  290.83 8.06 0 top
FD3  -  [FIDUCIAL_C40M80]  16.98 112.47 180 bottom
FD4  -  [FIDUCIAL_C40M80]  287.58 25.87 180 bottom
H1  -  [H_3P4]  82.2 113.55 0 top
H2  -  [H_3P4]  142 113.55 0 top
H3  -  [H_3P4]  142 91.4 0 top
H4  -  [H_3P4]  82.2 91.4 0 top
H5  -  [H_1P0N]  93.45 115.46 0 top
H6  -  [H_1P0N]  134.56 92.35 0 top
H7  -  [H_3P2]  275.9 102.5 0 top
H8  -  [H_3P2]  266.9 71.4 0 top
H9  -  [H_2P6-G]  234.1 134.2 0 top
H10  -  [H_3P8-G]  150.1 51.1 0 top
H12  -  [H_3P5-G]  270.6 50.25 0 top
H14  -  [H_2P6-G]  5.55 115.6 0 top
H15  -  [H_2P6-G]  5.55 98.7 0 top
H16  -  [H_2P6-G]  279.9 13.95 0 top
H18  -  [H_2P6-G]  12.05 116.5 0 top
H20  -  [H_3P1-G]  296.1 26.3 0 top
H21  -  [H_3P5-G]  220.15 77.75 0 top
H22  -  [H_3P5-G]  168.6 112.45 0 top
H23  -  [H_2P6-G]  8.6 74.35 0 top
H24  -  [H_2P6-G]  4.6 49.5 0 top
H25  -  [H_3P2]  43.6 132.55 0 top
H26  -  [H_3P2]  78 132.55 0 top
H27  -  [H_3P5-G]  35.55 47.35 0 top
H28  -  [H_3P5-G]  67.1 51.15 0 top
H29  -  [H_2P6-G]  289.05 132.9 0 top
H30  -  [H_2P3X2P7N]  4.6 44.5 90 top
H33  -  [H_2P6-G]  286.4 68.2 0 top
H37  -  [H_3P1-G]  150.1 134.3 0 top
H38  -  [H_2P6-G]  164.1 134.2 0 top
H39  -  [H_2P3N]  290.6 26.3 0 top
JAPS1  -  [CVILU_CF4218FH0R0-05-NH_18P-T]  264.56 108.17 180 top
JDB1  -  [ACES_50506-00641-P01_6P]  30.38 66.75 180 bottom
JDEG1  -  [HB_A531015-SCHR21_10P]  290.85 126.34 270 bottom
JDIMM1  -  [LCN_DAN05-Q0406-0103_260P]  76.22 61.9 180 bottom
JEDP1  -  [ACES_50398-04041-001_40P]  51.25 132.7 0 bottom
JESPI  -  [ACES_50506-01041-P01_10P]  247.45 54.75 180 bottom
JFAN1  -  [ACES_50271-0040N-001_4P]  236.55 122.66 90 bottom
JHDMI1  -  [ACON_HMRBL-A41L0F_19P-T]  11.45 81.1 90 bottom
JHP1  -  [SINGA_2SJ3095-085111F_6P]  287.5 41.1 90 bottom
JIR1  -  [E-T_4251K-F06N-40L_6P]  38.41 129.9 90 bottom
JKBTP1  -  [CVILU_CF5020FD0RK-05-NH_20P-T]  214.05 59.03 180 bottom
JLED1  -  [ACES_50209-0060N-P01_6P]  289.47 8.51 270 bottom
JLOM1  -  [SANTA_130470-19_13P-T]  283.87 100.18 270 bottom
JNGFF1  -  [LCN_DAN05-67306-0100_75P]  233.37 80.65 270 bottom
JNGFF2  -  [BELLW_80149-3221_67P]  230.37 111.75 270 bottom
JNGFF3  -  [LOTES_APCI0170-P001A_75P]  28.95 43.85 180 bottom
JRTC1  -  [ACES_50271-0020N-001_2P]  283.95 9.3 180 bottom
JSD1  -  [T-SOL_158-1240902600_23P-T]  286.05 59.37 90 top
JSIM1  -  [JAE_SF51S006V4DR1000Q_8P]  284.73 61.35 270 bottom
JSPI1  -  [E-T_6705K-Y20N-00L_20P]  165.45 91.91 270 bottom
JSPK1  -  [ACES_50278-0040N-001_4P]  286.02 19.15 270 bottom
JTAG1  -  [SHORTPADS]  248.05 99.71 180 top
JUART1  -  [CVILU_CI1804M1VRA-NH_4P]  128.81 132.36 180 bottom
JUSB1  -  [ACON_TCRA2-9U1U93_9P-T]  284.36 75.4 270 bottom
JUSB2  -  [ACON_TCRA2-9U1U93_9P-T]  15.83 65.95 90 bottom
JUSBC1  -  [JAE_DX07B024XJ1R1300_24P]  7.81 109.9 270 top
JUSH1  -  [CVILU_CF5026FD0RK-05-NH_26P-T]  233.45 59.02 180 bottom
JXDP1  -  [E-T_6601K-Y61N-04L_61P]  103.51 129.83 180 bottom
LA5  -  [MURAT_BLM15PX600SN1D_2P]  250.45 55.95 180 top
LA6  -  [MURAT_BLM15PX330SN1D_2P]  279.73 22.74 0 top
LA7  -  [MURAT_BLM15PX330SN1D_2P]  279.73 24.78 0 top
LA8  -  [MURAT_BLM15PX330SN1D_2P]  279.72 20.71 0 top
LA9  -  [MURAT_BLM15PX330SN1D_2P]  279.72 18.68 0 top
LA10  -  [MURAT_BLM15PX330SN1D_2P]  285 45.79 0 bottom
LA11  -  [MURAT_BLM15PX330SN1D_2P]  285 44.59 0 bottom
LA12  -  [MURAT_BLM15PX600SN1D_2P]  254.15 66.39 90 top
LA13  -  [TAI-T_HCB2012VF-601T20_2P]  263.36 63 90 top
LA14  -  [MURAT_BLM15PX600SN1D_2P]  261.71 65.56 90 top
LC1  -  [MURAT_BLM15GA750SN1D_2P]  138.07 98.37 270 top
LC2  -  [MURAT_BLM15GA750SN1D_2P]  129.94 120.08 270 bottom
LED3  -  [LED_LTW-C193DC-C_2P]  292.97 128.5 0 top
LI3  -  [PANAS_EXC24CQ900U_4P]  24.21 62.54 90 bottom
LI7  -  [PANAS_EXC24CQ900U_4P]  277.59 74.26 270 bottom
LI8  -  [INPAQ_HCM2012GA900AE_4P]  234.63 106.37 180 top
LI9  -  [INPAQ_HCM2012GA900AE_4P]  228.46 78.24 0 bottom
LI16  -  [INPAQ_HCM2012GA900AE_4P]  234.62 104.21 180 top
LI17  -  [INPAQ_HCM2012GA900AE_4P]  229.89 100.3 90 top
LL1  -  [TAIYO_BRC2012T4R7MD_2P]  251.42 125.07 90 bottom
LT11  -  [MURAT_BLM15PX600SN1D_2P]  32.85 97.95 90 top
LT13  -  [MURAT_BLM15PX600SN1D_2P]  34.56 99.07 180 top
LV1  -  [MURAT_BLM15PX221SN1D_2P]  62.52 130.04 270 top
LV3  -  [TAIYO_MCF12102G900-T_4P]  18.94 81.25 180 bottom
LV6  -  [TAIYO_MCF12102G900-T_4P]  18.94 83.09 180 bottom
LV9  -  [TAIYO_MCF12102G900-T_4P]  18.94 86.77 180 bottom
LV12  -  [TAIYO_MCF12102G900-T_4P]  18.94 84.93 180 bottom
LV27  -  [PANAS_EXC24CQ900U_4P]  52.6 121.61 0 top
LV31  -  [MURAT_LQG15HN12NJ02D_2P]  18.77 80.53 180 bottom
LV32  -  [MURAT_LQG15HN12NJ02D_2P]  18.77 81.42 180 bottom
LV33  -  [MURAT_LQG15HN12NJ02D_2P]  18.77 82.37 180 bottom
LV34  -  [MURAT_LQG15HN12NJ02D_2P]  18.77 83.26 180 bottom
LV35  -  [MURAT_LQG15HN12NJ02D_2P]  18.77 86.05 180 bottom
LV36  -  [MURAT_LQG15HN12NJ02D_2P]  18.77 86.94 180 bottom
LV37  -  [MURAT_LQG15HN12NJ02D_2P]  18.77 84.21 180 bottom
LV38  -  [MURAT_LQG15HN12NJ02D_2P]  18.77 85.1 180 bottom
LZ1  -  [PANAS_EXC24CQ900U_4P]  56.17 121.28 90 top
NOREF  -  []  4.6 49.5 90 top
NOREF#2  -  []  296.1 26.3 270 top
NOREF#3  -  []  82.2 91.4 0 top
NOREF#4  -  []  77.91 77.8 0 top
NOREF#5  -  []  286.4 68.2 0 top
NOREF#6  -  []  209.48 63.89 0 top
NOREF#7  -  []  67.1 51.15 180 top
NOREF#8  -  []  234.1 134.2 0 top
NOREF#9  -  []  103.95 72.88 0 top
NOREF#10  -  []  8.6 74.35 90 top
NOREF#11  -  []  114.69 68.57 0 top
NOREF#12  -  []  266.9 71.4 0 top
NOREF#13  -  []  142 113.55 0 top
NOREF#14  -  []  86.68 69.59 0 top
NOREF#15  -  []  275.9 102.5 0 top
NOREF#16  -  []  142 91.4 0 top
NOREF#17  -  []  289.05 132.9 0 top
NOREF#18  -  []  82.2 113.55 0 top
NOREF#19  -  []  150.1 51.1 180 top
NOREF#20  -  []  36.98 177.87 0 top
NOREF#21  -  []  132.46 1.89 0 top
NOREF#22  -  []  33.93 171.65 0 top
NOREF#23  -  []  279.9 13.95 90 top
NOREF#24  -  []  278.53 3 0 top
NOREF#25  -  []  88.28 43.33 180 bottom
NOREF#26  -  []  78 132.55 180 bottom
NOREF#27  -  []  127.21 73.07 180 bottom
NOREF#28  -  []  204.68 65.48 180 bottom
NOREF#29  -  []  125.02 40.97 180 bottom
PBATT1  -  [DEREN_40-42251-01001RHF_10P-T]  173.1 57.47 135 bottom
PC1  -  [C_0402]  167.6 56.77 90 top
PC2  -  [C_0402]  283.03 8.96 0 top
PC3  -  [C_0603]  285.9 13.16 0 top
PC4  -  [C_0603]  46.76 110.88 180 bottom
PC5  -  [C_0603]  40.98 118.95 270 bottom
PC6  -  [C_0603]  48.06 120.36 180 bottom
PC7  -  [C_0603]  42.25 118.95 270 bottom
PC8  -  [C_0805]  44.31 114.69 180 bottom
PC9  -  [C_0402]  55.19 115.71 0 top
PC10  -  [C_0402]  63.59 118.24 90 bottom
PC11  -  [C_0603]  63.46 120.15 90 bottom
PC100  -  [C_0402]  154.39 73.66 90 top
PC102  -  [C_0603]  157.57 71.64 90 bottom
PC103  -  [C_0402]  153.26 72.97 180 top
PC104  -  [C_0805]  153.08 70.43 180 bottom
PC105  -  [C_0805]  153.08 72.15 180 bottom
PC106  -  [C_0805]  167.07 76.34 0 bottom
PC107  -  [C_0805]  167.07 76.34 0 top
PC108  -  [C_0805]  167.07 74.56 0 top
PC109  -  [C_0805]  167.07 74.56 0 bottom
PC110  -  [C_0805]  167.07 78.05 0 top
PC111  -  [C_0603]  156.42 79.03 180 top
PC112  -  [C_0603]  162.77 71.26 90 bottom
PC113  -  [C_0402]  154.33 78.8 90 bottom
PC114  -  [C_0603]  187.6 50.87 90 bottom
PC115  -  [C_0402]  180.5 51.57 180 bottom
PC116  -  [C_0402]  180.5 52.46 180 bottom
PC117  -  [C_0805]  179.86 53.58 90 bottom
PC118  -  [C_0805]  181.57 53.58 90 bottom
PC119  -  [C_0603]  186.14 57.22 0 top
PC120  -  [C_0805]  198.27 58.34 90 bottom
PC121  -  [C_0805]  197.76 52.74 270 top
PC122  -  [C_0805]  199.48 52.74 270 bottom
PC123  -  [C_0805]  197.76 52.74 270 bottom
PC124  -  [C_0805]  196.56 58.34 90 bottom
PC125  -  [C_0603]  190.14 56.02 180 top
PC126  -  [C_0603]  185.13 57.22 180 top
PC127  -  [C_0402]  184.86 58.93 90 bottom
PC128  -  [C_0402]  153.44 78.8 90 bottom
PC129  -  [C_0805]  167.07 78.05 0 bottom
PC130  -  [C_0805]  199.48 52.74 270 top
PC200  -  [C_0805]  66.67 74.05 0 top
PC201  -  [C_0805]  66.67 74.05 0 bottom
PC202  -  [C_0402]  67.13 75.39 0 bottom
PC203  -  [C_0402]  67.13 75.39 0 top
PC204  -  [C_0603]  67.24 70.18 90 top
PC205  -  [C_0603]  63.02 67.19 0 bottom
PC206  -  [C_0402]  64.49 69.48 180 bottom
PC207  -  [C_0402]  64.93 69.16 180 top
PC208  -  [C_0402]  63.96 70.81 0 top
PC209  -  [C_0603]  70.57 67.97 0 top
PC210  -  [C_0603]  68.92 57.41 270 bottom
PC211  -  [C_0603]  67.71 57.41 270 bottom
PC212  -  [C_0603]  66.51 57.41 270 bottom
PC213  -  [C_0603]  68.92 57.41 270 top
PC214  -  [C_0603]  67.71 57.41 270 top
PC216  -  [C_0402]  70 57.17 270 bottom
PC217  -  [C_0402]  70 57.17 270 top
PC218  -  [C_0402]  70.67 72.53 0 top
PC219  -  [C_0603]  70.57 69.18 0 top
PC221  -  [C_0402]  70 75 90 top
PC222  -  [C_0402]  72.67 75 90 top
PC301  -  [C_0402]  153.95 82.78 0 top
PC302  -  [C_0603]  157.69 80.85 90 top
PC303  -  [C_0402]  153.95 81.89 0 top
PC304  -  [C_0603]  154.07 83.83 0 top
PC305  -  [C_0603]  152.3 82.69 270 bottom
PC306  -  [C_0603]  151.03 82.69 270 bottom
PC307  -  [C_0402]  154.34 87.96 180 bottom
PC308  -  [C_0603]  162.49 86.12 0 top
PC309  -  [C_0603]  162.49 87.83 0 top
PC310  -  [C_0603]  162.49 87.83 0 bottom
PC311  -  [C_0603]  162.49 86.12 0 bottom
PC312  -  [C_0603]  152.8 84.85 180 bottom
PC313  -  [C_0603]  153.76 86.69 0 top
PC401  -  [C_0402]  137.44 130.17 90 top
PC402  -  [C_0402]  142.84 128.14 90 top
PC403  -  [C_0603]  144.68 130.19 90 bottom
PC404  -  [C_0603]  144.68 130.19 90 top
PC406  -  [C_0603]  134.77 131.01 180 bottom
PC407  -  [C_0603]  134.77 129.8 180 bottom
PC408  -  [C_0402]  145.76 130.17 90 top
PC409  -  [C_0402]  145.76 130.17 90 bottom
PC410  -  [C_0402]  142.21 133.74 180 bottom
PC411  -  [C_0402]  163.71 125.74 0 top
PC412  -  [C_0603]  160.62 128.73 90 bottom
PC413  -  [C_0603]  160.62 128.73 90 top
PC415  -  [C_0603]  150.65 128.66 180 bottom
PC416  -  [C_0603]  150.65 127.46 180 top
PC417  -  [C_0402]  161.69 128.65 90 bottom
PC418  -  [C_0402]  161.69 128.65 90 top
PC419  -  [C_0402]  155.4 127.26 0 top
PC420  -  [C_0402]  158.15 132.09 180 bottom
PC422  -  [C_0603]  134.77 128.6 180 bottom
PC424  -  [C_0603]  150.65 127.46 180 bottom
PC501  -  [C_0603]  176.38 60.41 225 bottom
PC502  -  [C_0603]  169.01 66.06 45 bottom
PC503  -  [C_0402]  173.55 68.9 135 bottom
PC504  -  [C_0603]  177.23 59.56 225 bottom
PC505  -  [C_0402]  175.16 66.29 45 bottom
PC506  -  [C_0402]  171.06 64.05 135 bottom
PC513  -  [C_0402]  150.26 56.58 90 top
PC514  -  [C_0603]  151.43 62.24 180 top
PC515  -  [C_0402]  146.07 60.86 270 top
PC516  -  [C_0603]  148.3 62.03 90 top
PC601  -  [C_0402]  49.86 101.55 0 bottom
PC602  -  [C_0402]  44.99 92.85 180 bottom
PC603  -  [C_0603]  44.73 96.59 180 bottom
PC604  -  [C_0603]  44.73 97.8 180 bottom
PC605  -  [C_0402]  47.97 94.58 270 bottom
PC606  -  [C_D]  65.49 87.2 0 bottom
PC608  -  [C_0805]  64.48 114.6 90 bottom
PC611  -  [C_0603]  60.09 112.91 90 top
PC612  -  [C_0805]  64.48 114.6 90 top
PC613  -  [C_0402]  47.39 92.04 270 bottom
PC614  -  [C_0402]  50.95 92.48 270 bottom
PC616  -  [C_0402]  49.36 93.37 270 bottom
PC617  -  [C_0402]  50.25 88.92 270 top
PC618  -  [C_0402]  49.6 89.8 0 bottom
PC619  -  [C_0402]  49.6 88.91 0 bottom
PC620  -  [C_0402]  51.14 88.9 90 top
PC621  -  [C_0402]  46.62 88.02 0 top
PC622  -  [C_0603]  67.33 116.09 180 top
PC624  -  [C_0402]  53.24 88.77 90 bottom
PC625  -  [C_0402]  52.67 92.77 90 bottom
PC626  -  [C_0402]  52.35 88.77 90 bottom
PC627  -  [C_0402]  52.03 88.83 90 top
PC628  -  [C_0402]  50 97.24 270 bottom
PC629  -  [C_0402]  52.67 97.24 270 bottom
PC630  -  [C_0402]  54.51 97.22 90 top
PC631  -  [C_0402]  48.21 96.34 0 bottom
PC632  -  [C_0402]  48.11 99.39 180 bottom
PC633  -  [C_0402]  49.4 99.4 180 top
PC636  -  [C_0402]  50.87 94.88 0 bottom
PC637  -  [C_0402]  49.4 100.29 180 top
PC639  -  [C_0402]  55.38 94.56 0 top
PC640  -  [C_0402]  51.64 100.28 0 bottom
PC641  -  [C_0402]  53.25 90.56 180 bottom
PC642  -  [C_0402]  55.4 96.39 90 bottom
PC643  -  [C_0402]  51.78 97.24 270 bottom
PC644  -  [C_0402]  47.62 100.29 270 top
PC645  -  [C_0402]  57.17 97.24 270 top
PC646  -  [C_0402]  54.51 96.39 90 bottom
PC647  -  [C_0402]  57.17 94.58 270 top
PC649  -  [C_0402]  51.22 99.39 180 top
PC650  -  [C_0402]  52.09 100.29 270 top
PC651  -  [C_0402]  56.3 95.45 180 top
PC652  -  [C_0402]  51.22 100.28 180 top
PC653  -  [C_0402]  54.51 95.44 90 top
PC654  -  [C_0402]  56.3 96.34 180 top
PC655  -  [C_0603]  52.22 110.63 0 bottom
PC656  -  [C_0805]  54.67 103.58 0 top
PC657  -  [C_0805]  54.67 105.29 0 top
PC658  -  [C_0805]  54.67 105.29 0 bottom
PC659  -  [C_0402]  54.48 107.16 0 top
PC660  -  [C_0402]  54.48 108.05 0 top
PC661  -  [C_0402]  60.15 110.31 0 bottom
PC662  -  [C_0603]  58.89 104.15 90 bottom
PC663  -  [C_0805]  54.67 103.58 0 bottom
PC664  -  [C_0805]  66.83 90.16 90 top
PC665  -  [C_0805]  66.83 90.16 90 bottom
PC671  -  [C_0603]  59.35 87.65 90 bottom
PC672  -  [C_0805]  65.05 90.16 90 bottom
PC673  -  [C_0805]  65.05 90.16 90 top
PC677  -  [C_0402]  60.15 94.05 0 top
PC678  -  [C_0603]  64.03 95.58 270 top
PC679  -  [C_0402]  63.71 89.98 90 top
PC680  -  [C_0402]  54.48 109.83 0 top
PC685  -  [C_0402]  62.19 114.9 270 top
PC686  -  [C_0402]  54.48 108.94 0 top
PC688  -  [C_0402]  62.83 89.98 90 top
PC902  -  [C_0402]  45.82 80.4 180 top
PC903  -  [C_0402]  45.82 80.4 180 bottom
PC904  -  [C_0805]  46.21 77.35 180 bottom
PC905  -  [C_0805]  46.21 79.07 180 bottom
PC906  -  [C_0805]  46.21 79.07 180 top
PC909  -  [C_B2]  46.74 74.88 0 bottom
PC910  -  [C_B2]  50.21 74.88 180 bottom
PC911  -  [C_0805]  46.21 77.35 180 top
PC913  -  [C_0805]  59.23 72.65 180 top
PC914  -  [C_0805]  59.23 70.94 180 top
PC915  -  [C_0805]  59.23 76.08 180 top
PC916  -  [C_0805]  59.23 70.94 180 bottom
PC917  -  [C_0805]  59.23 72.65 180 bottom
PC918  -  [C_0805]  59.23 74.37 180 bottom
PC919  -  [C_0805]  59.23 76.08 180 bottom
PC920  -  [C_0805]  59.23 74.37 180 top
PC925  -  [C_0402]  55.27 60.96 90 bottom
PC926  -  [C_0402]  55.51 59.68 270 bottom
PC927  -  [C_0402]  56.45 59.12 0 bottom
PC928  -  [C_0402]  59.22 77.42 180 top
PC929  -  [C_0402]  59.22 77.42 180 bottom
PC930  -  [C_0603]  58.25 62.62 270 top
PC931  -  [C_0603]  54.44 58.3 90 bottom
PC932  -  [C_0402]  58.76 57.91 90 bottom
PC933  -  [C_0402]  53.85 57.34 0 bottom
PC934  -  [C_0603]  62.19 56.84 180 top
PC935  -  [C_0805]  175.54 51.69 270 top
PC936  -  [C_0805]  177.25 51.69 270 top
PC937  -  [C_0402]  59.27 52.07 90 top
PC938  -  [C_0402]  53.85 54.67 0 bottom
